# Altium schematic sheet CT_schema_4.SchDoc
size 297 x 173 mm
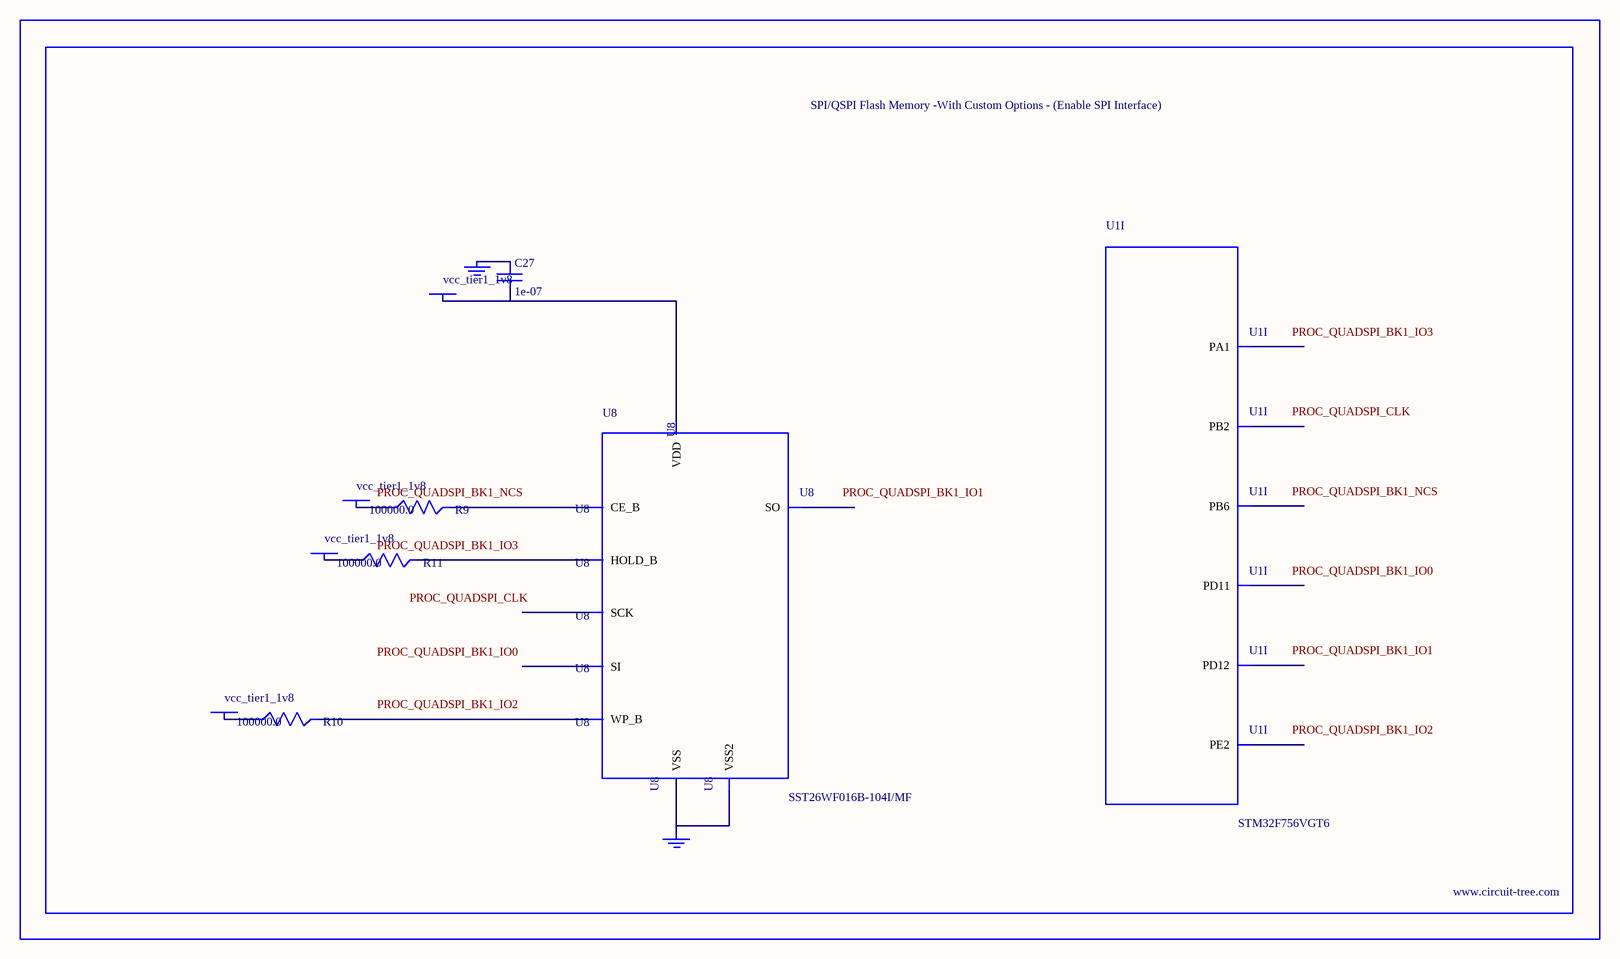
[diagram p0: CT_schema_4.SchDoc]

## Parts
BORDER3  (no value)
C27  1e-07  [C0402]
GND_INSTANCE_3_0  (no value)
GND_INSTANCE_3_1  (no value)
POWER_INSTANCE_3_0  vcc_tier1_1v8
POWER_INSTANCE_3_1  vcc_tier1_1v8
POWER_INSTANCE_3_2  vcc_tier1_1v8
POWER_INSTANCE_3_3  vcc_tier1_1v8
R9  100000.0  [R0603]
R10  100000.0  [R0603]
R11  100000.0  [R0603]
U1  STM32F756VGT6  [LQFP100]  (part I of 10)
U8  SST26WF016B-104I/MF  [WFDN-8]

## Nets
NetC27_1: C27.1 GND_INSTANCE_3_0.0(GND)
NetC27_2: C27.2 POWER_INSTANCE_3_3.0(PWR) U8.8(VDD)
NetGND_INSTANCE_3_1_0: GND_INSTANCE_3_1.0(GND) U8.4(VSS) U8.9(VSS2)
NetPOWER_INSTANCE_3_0_0: POWER_INSTANCE_3_0.0(PWR) R9.1
NetPOWER_INSTANCE_3_1_0: POWER_INSTANCE_3_1.0(PWR) R10.1
NetPOWER_INSTANCE_3_2_0: POWER_INSTANCE_3_2.0(PWR) R11.1
NetR9_2: R9.2 U8.1(CE_B)
NetR10_2: R10.2 U8.3(WP_B)
NetR11_2: R11.2 U8.7(HOLD_B)

Not connected (* = marked no-connect by the designer): U1 1(PE2) 23(PA1) 36(PB2) 58(PD11) 59(PD12) 92(PB6); U8 2(SO) 5(SI) 6(SCK)

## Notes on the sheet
- Labels drawn without touching a wire or pin: PROC_QUADSPI_BK1_IO0, PROC_QUADSPI_BK1_IO1, PROC_QUADSPI_BK1_IO2, PROC_QUADSPI_BK1_IO3, PROC_QUADSPI_BK1_NCS, PROC_QUADSPI_CLK

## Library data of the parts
BORDER3 = BORDER_PAGE3
C27 = C0402C104K3RACTU
GND_INSTANCE_3_0 GND_INSTANCE_3_1 = GND
POWER_INSTANCE_3_0-POWER_INSTANCE_3_3 = PWR
R9-R11 = RC0603JR-07100KL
